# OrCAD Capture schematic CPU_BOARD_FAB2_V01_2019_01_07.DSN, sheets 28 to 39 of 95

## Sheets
28 079 P3V3_STBY: size B
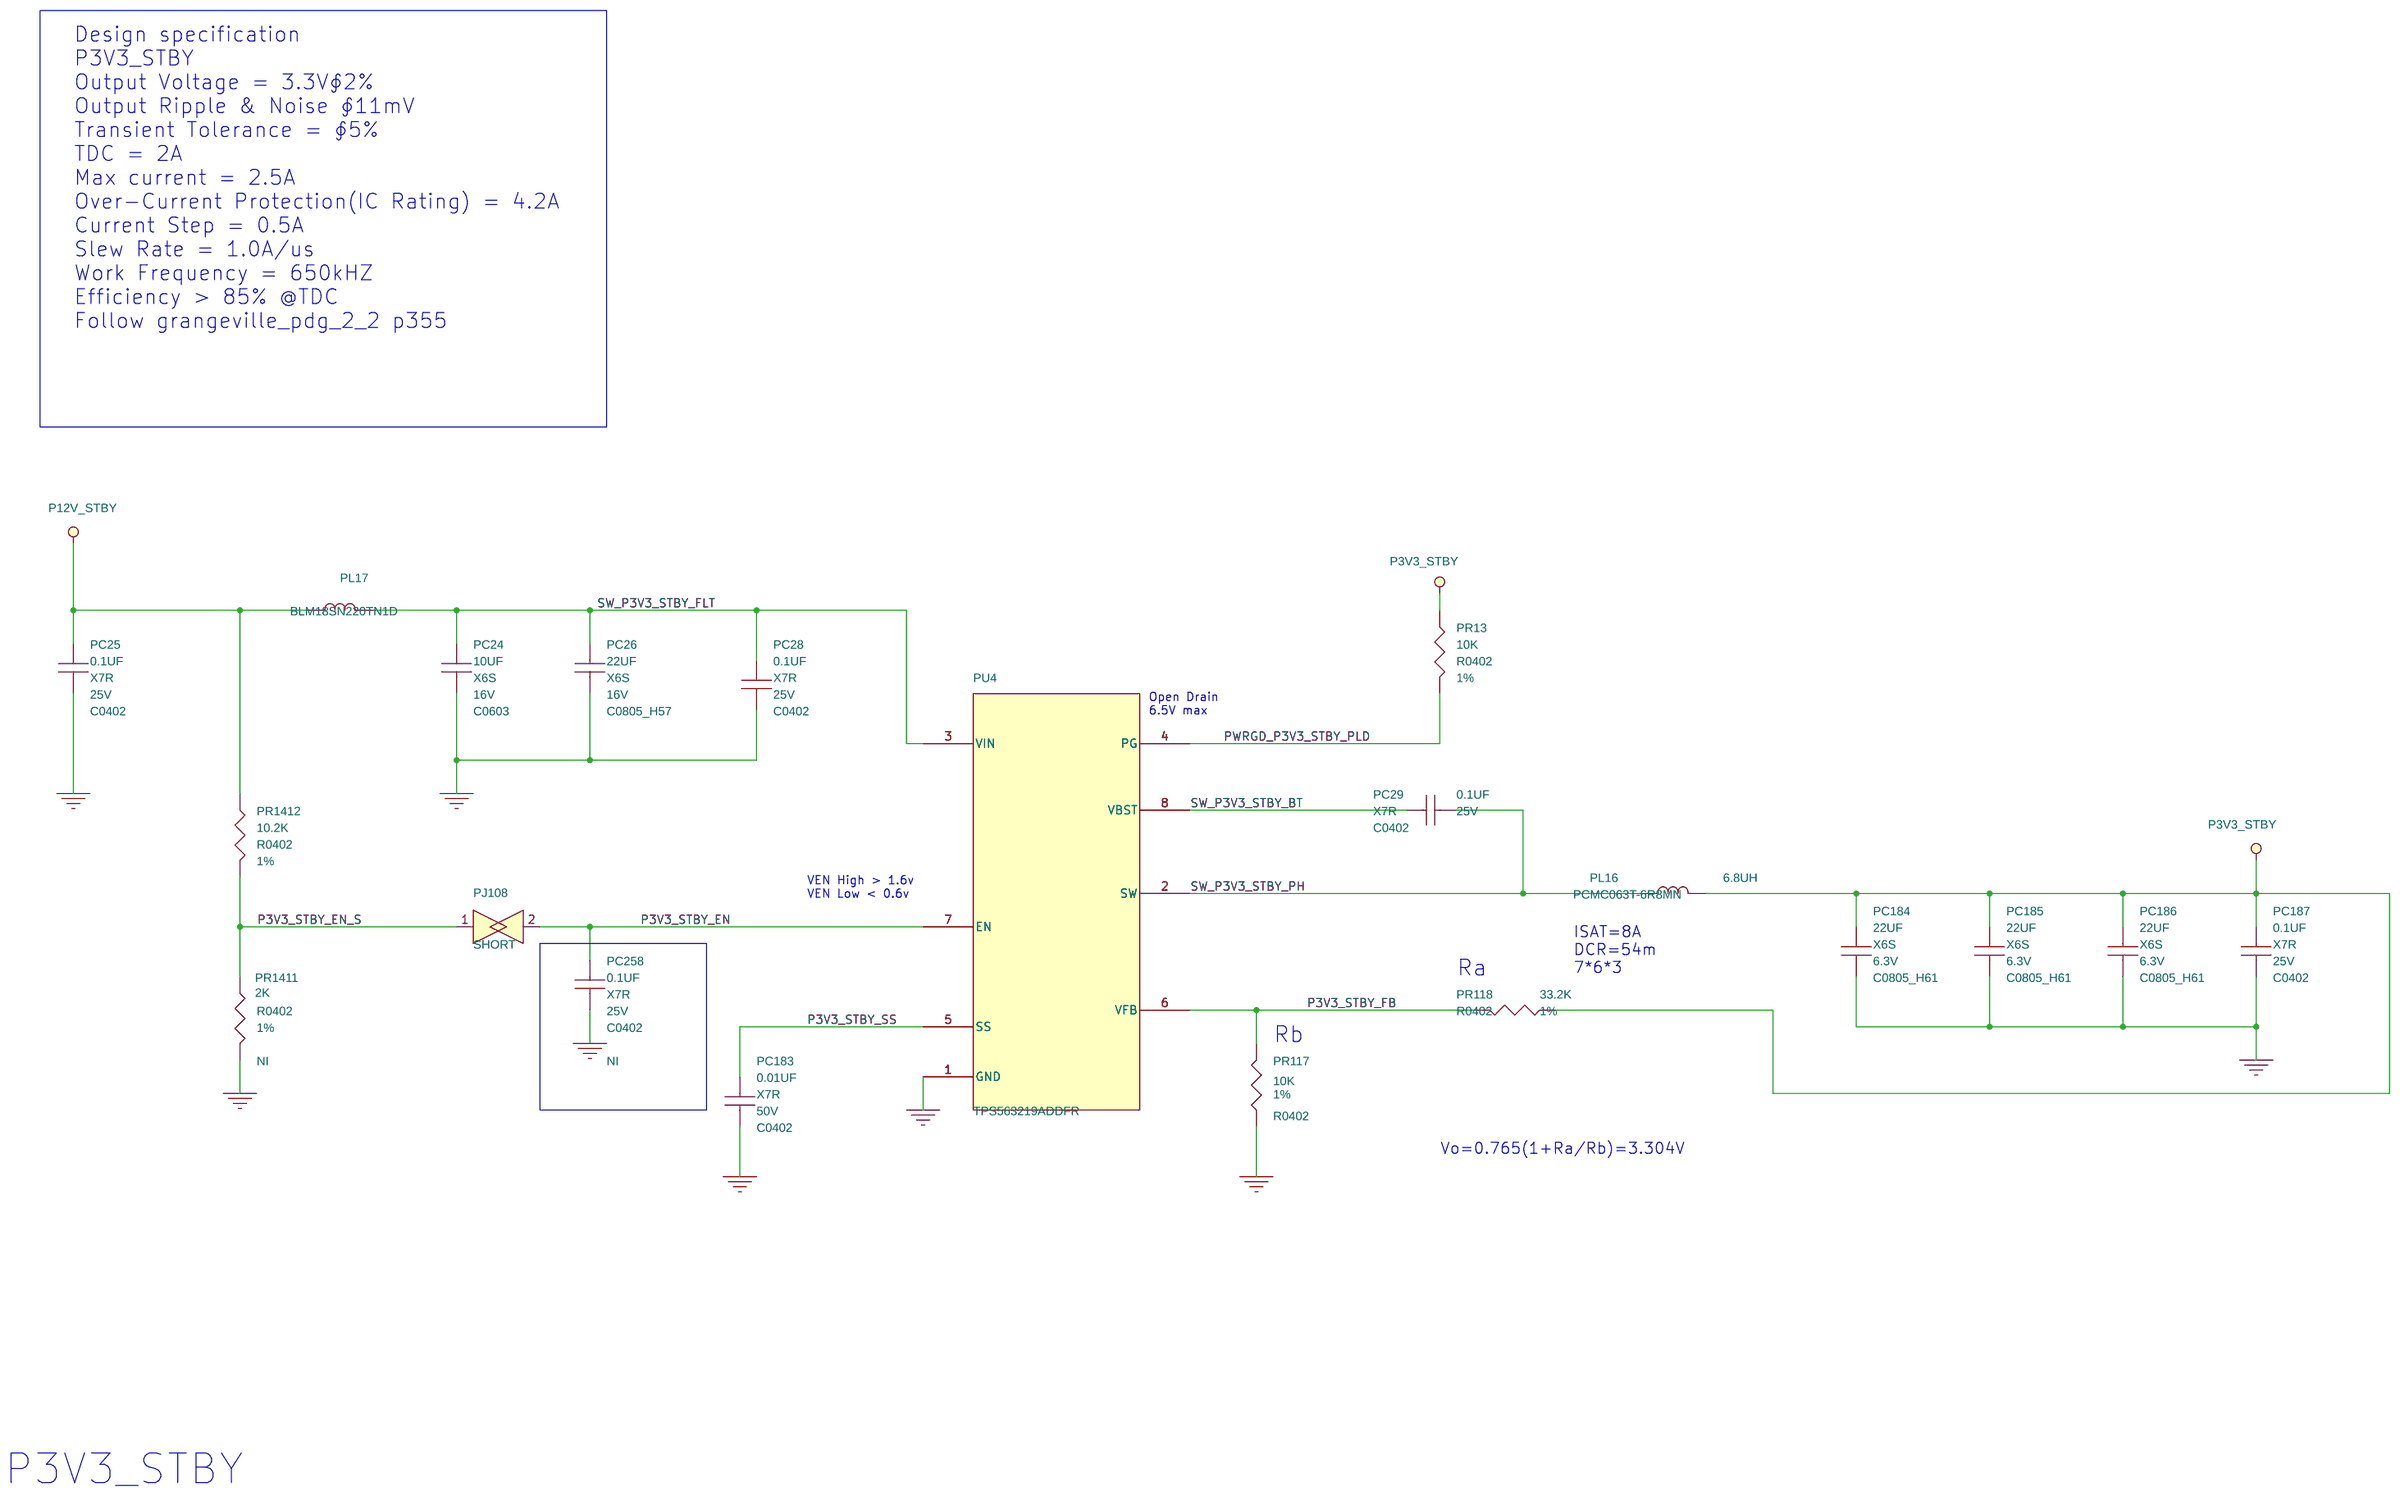
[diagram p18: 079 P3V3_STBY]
29 078 BLANK
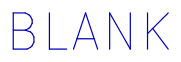
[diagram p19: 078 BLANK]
30 014 SPI_STRUCTURE
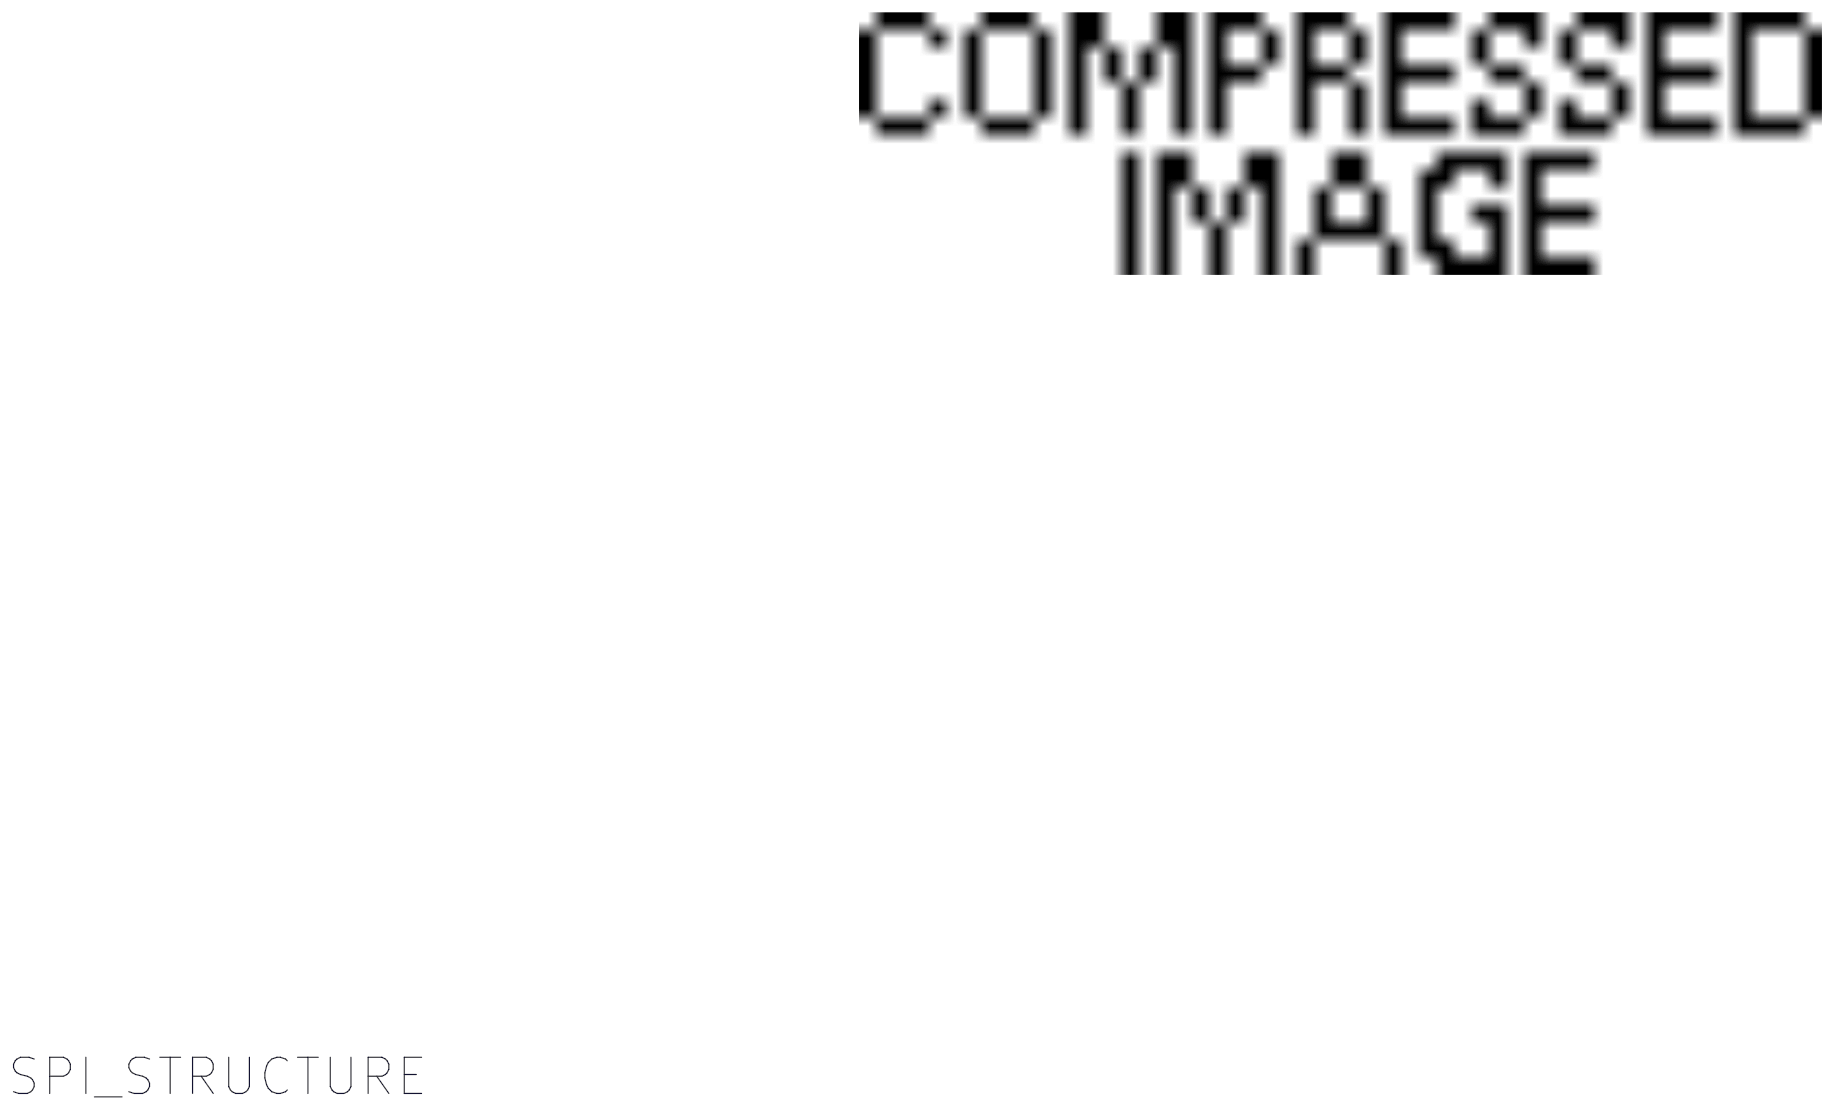
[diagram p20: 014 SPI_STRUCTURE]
31 083 P1V5_PCH: size B
32 090 P3V3 SWITCH: size B
33 001 COVER PAGE
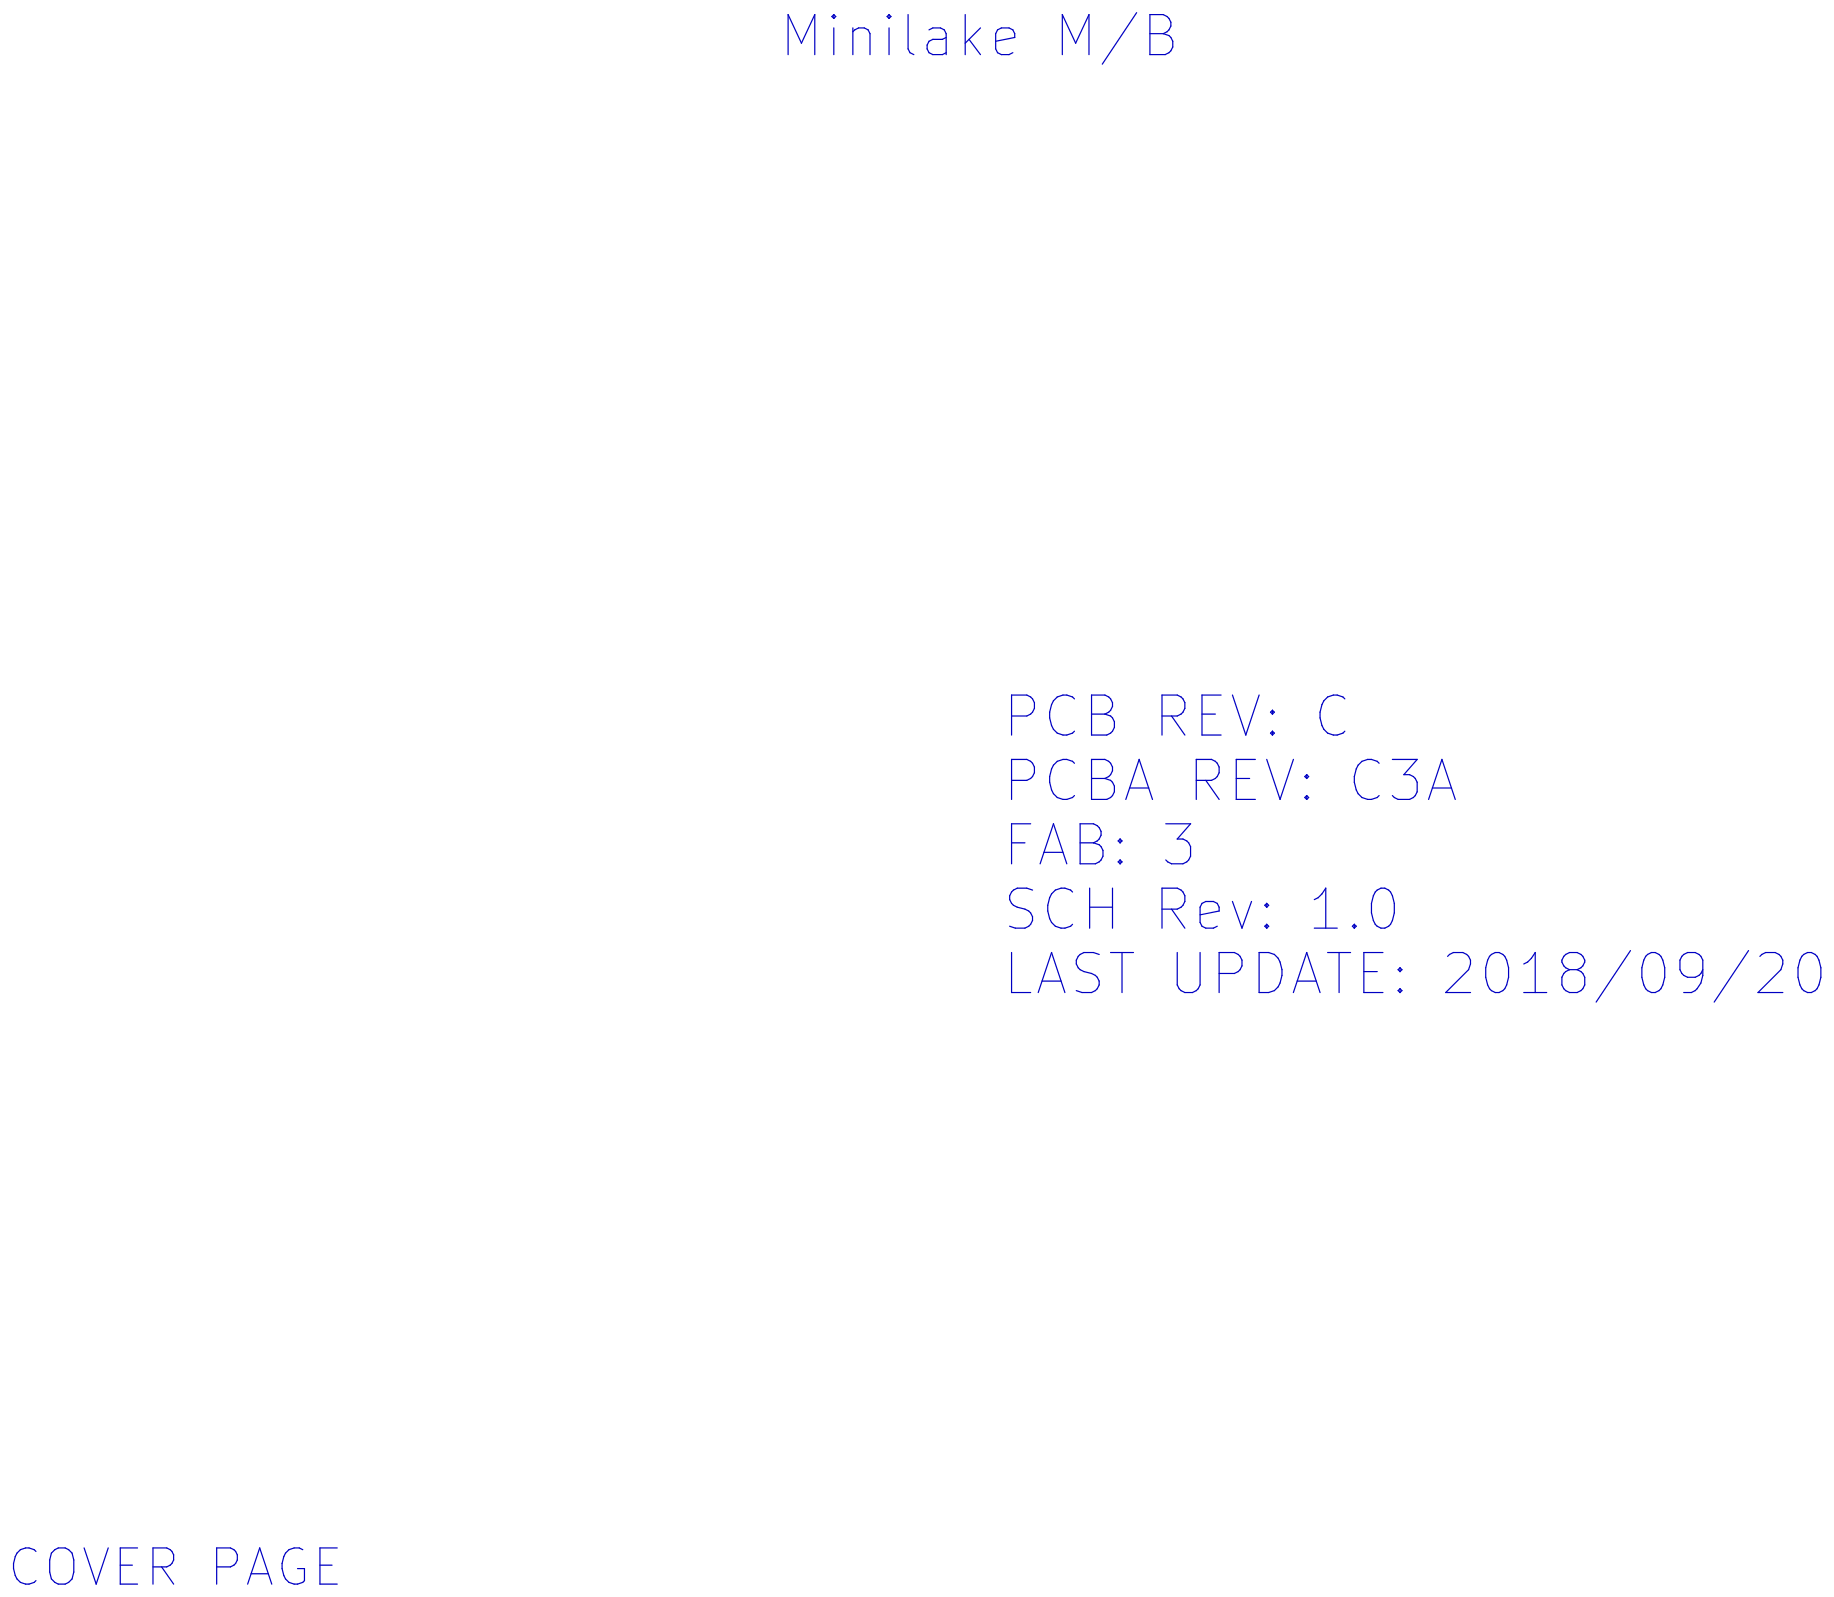
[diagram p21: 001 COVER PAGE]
34 002 PAGE INDEX
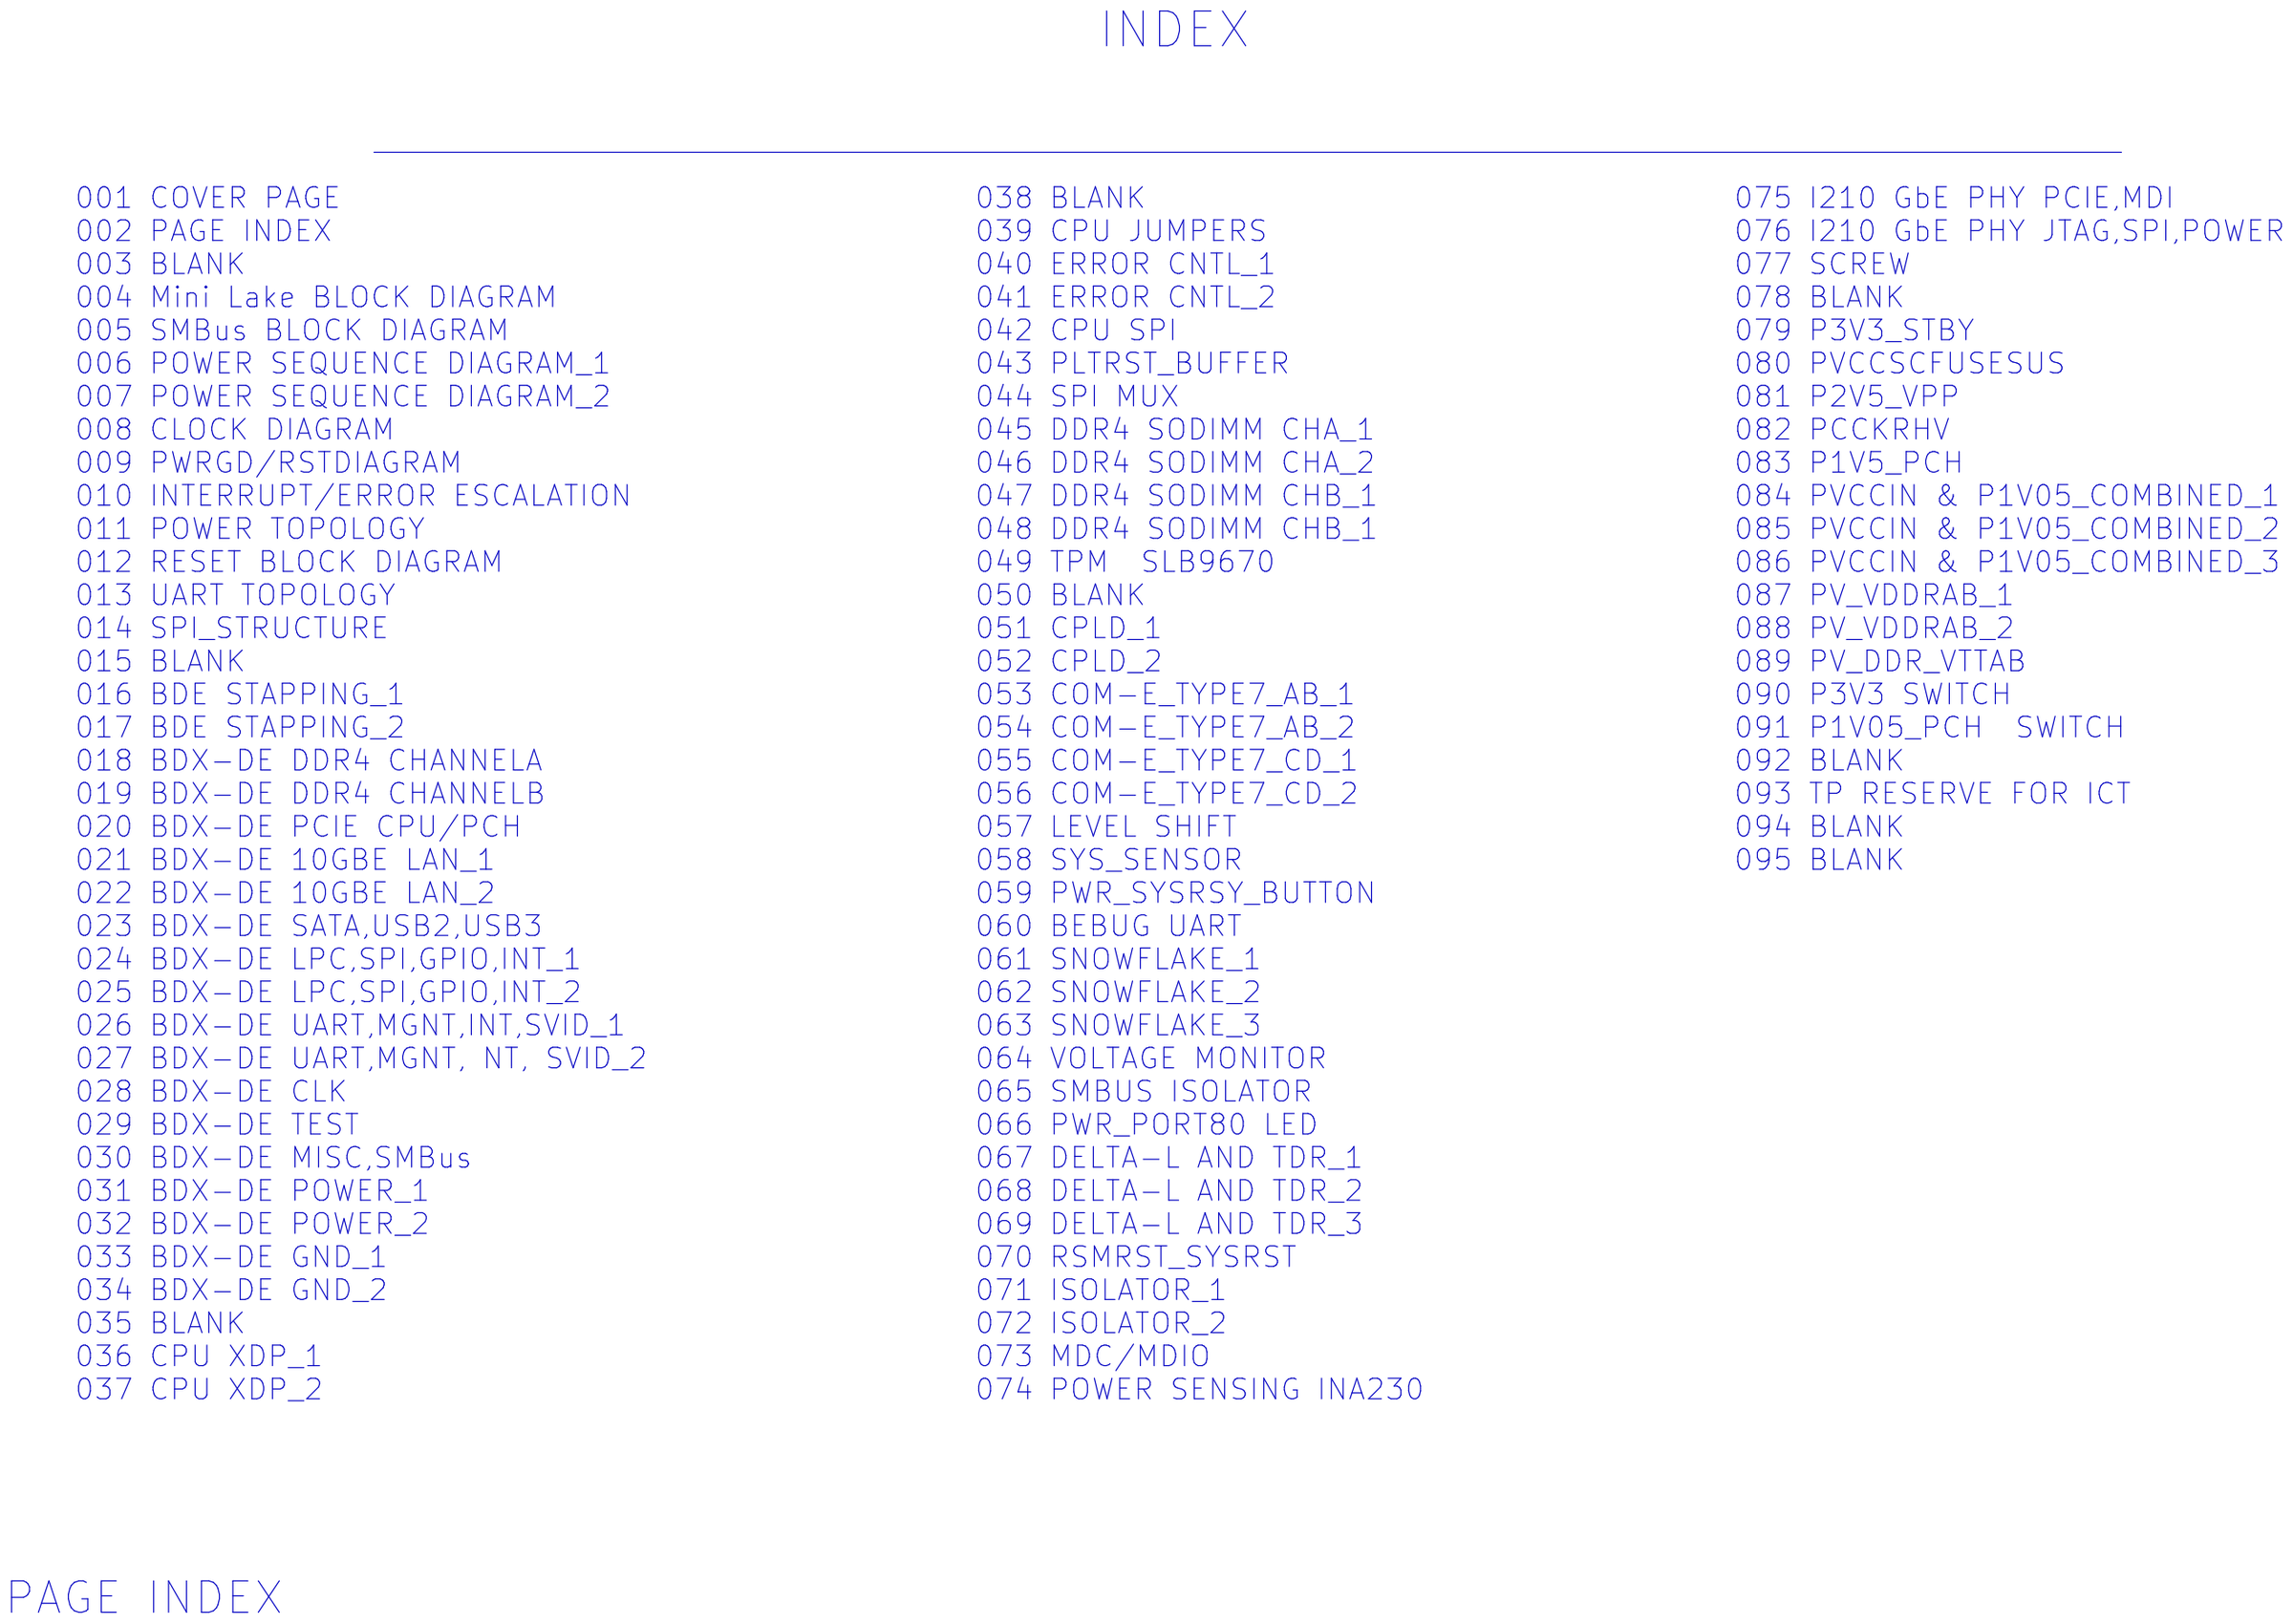
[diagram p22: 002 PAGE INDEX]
35 003 BLANK
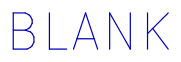
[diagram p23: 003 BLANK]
36 005 SMBus BLOCK DIAGRAM
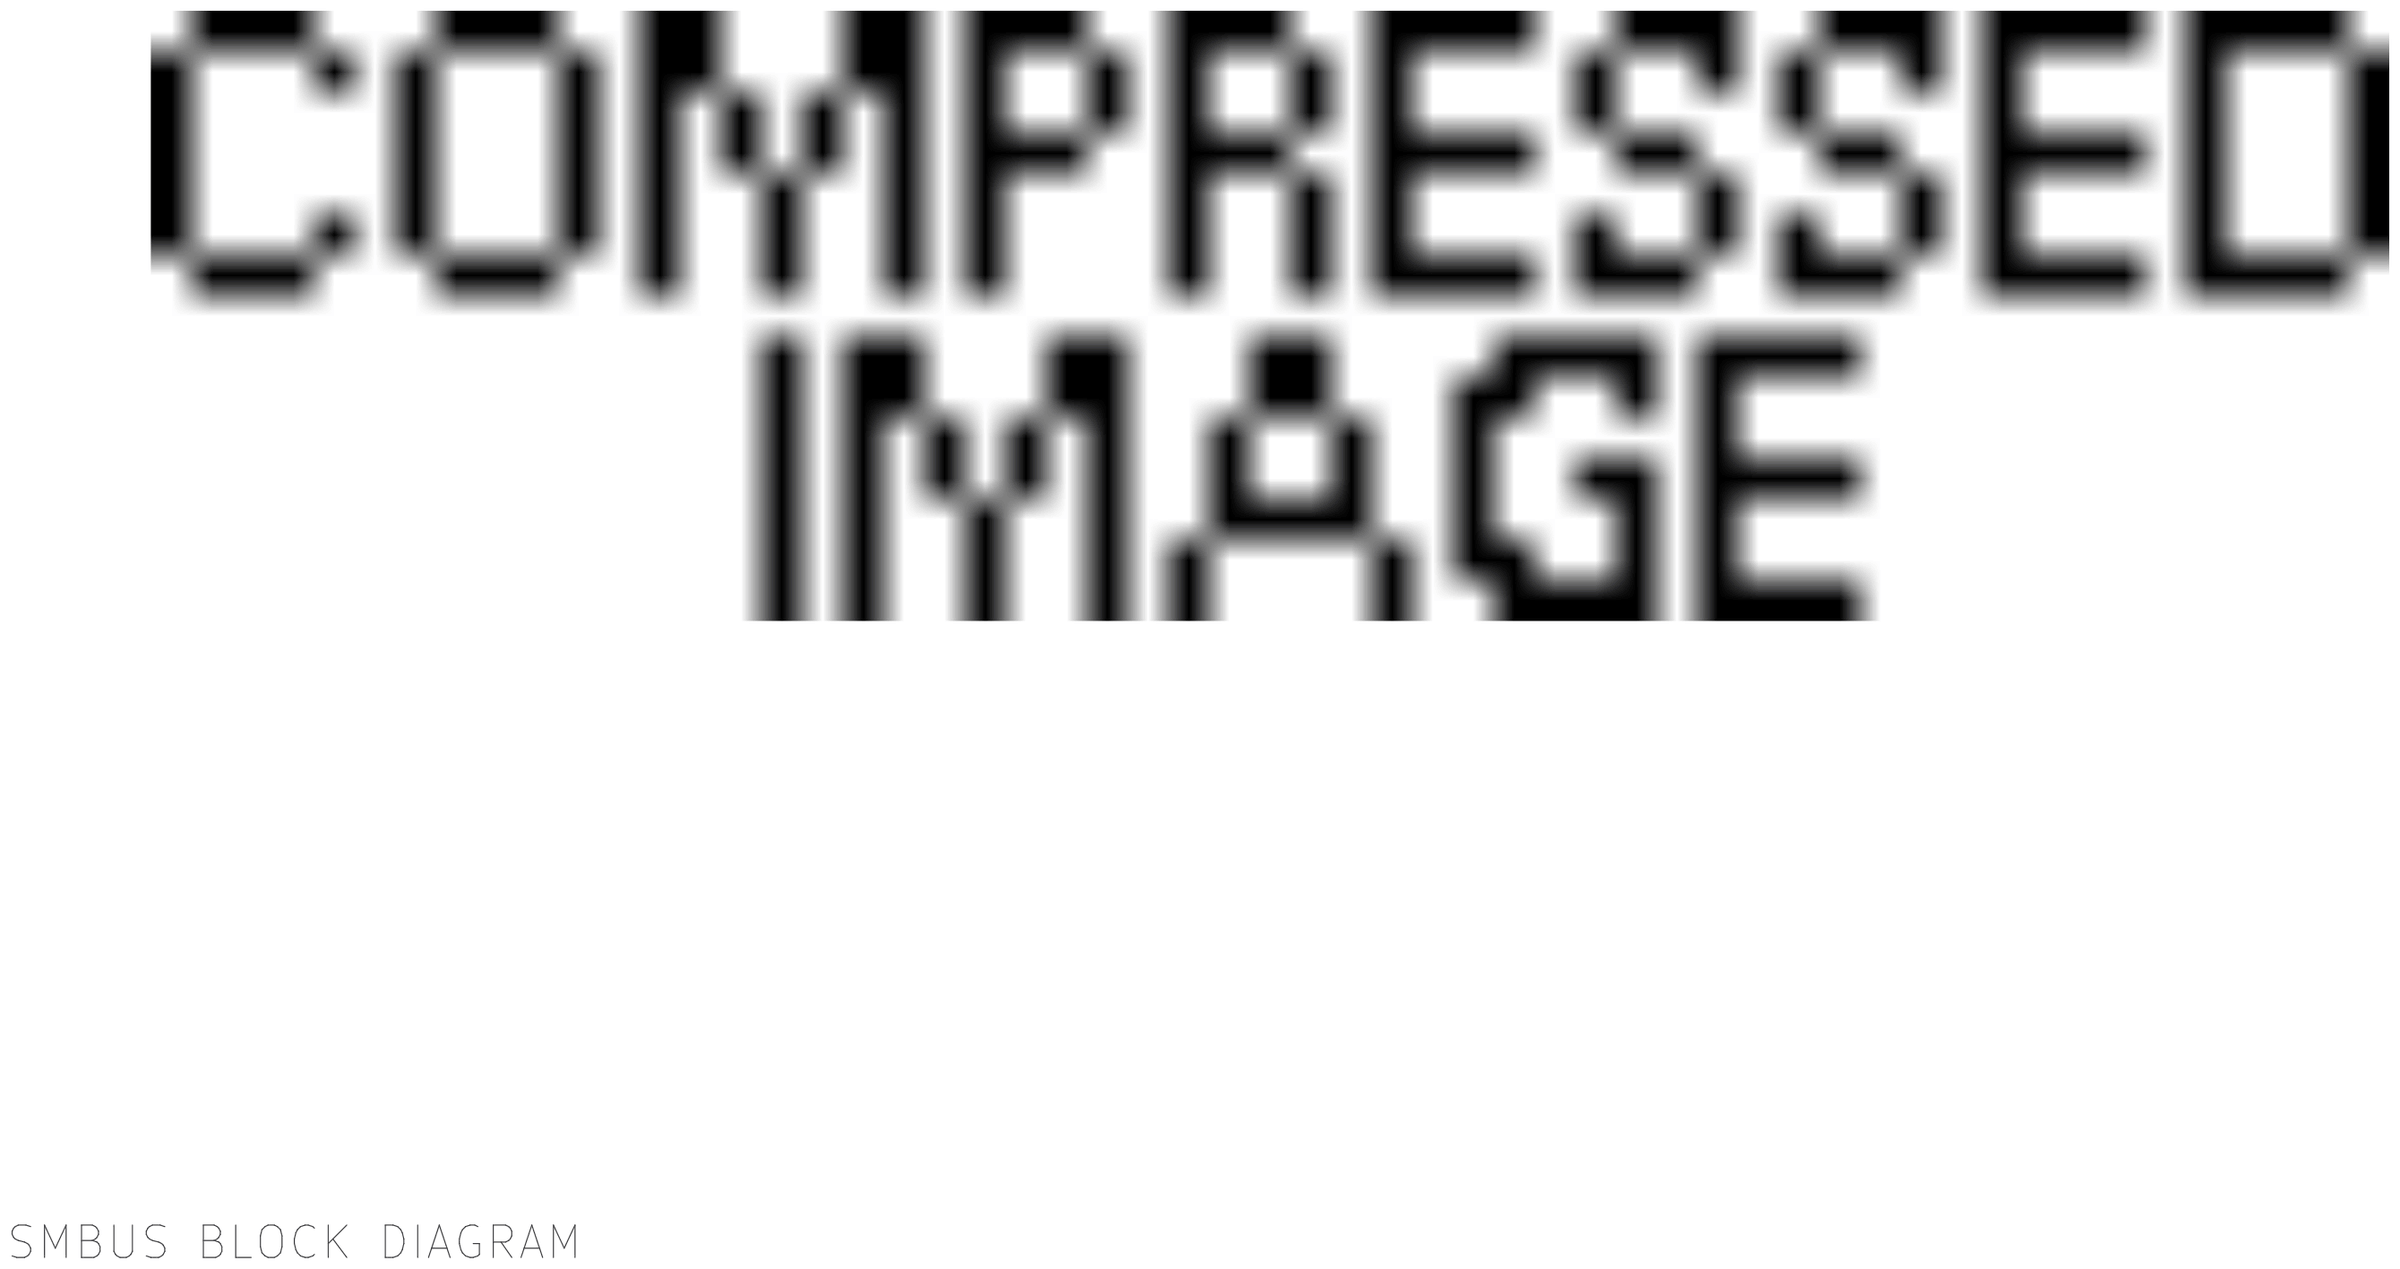
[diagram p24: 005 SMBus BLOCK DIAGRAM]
37 006 POWER SEQUENCE DIAGRAM_1
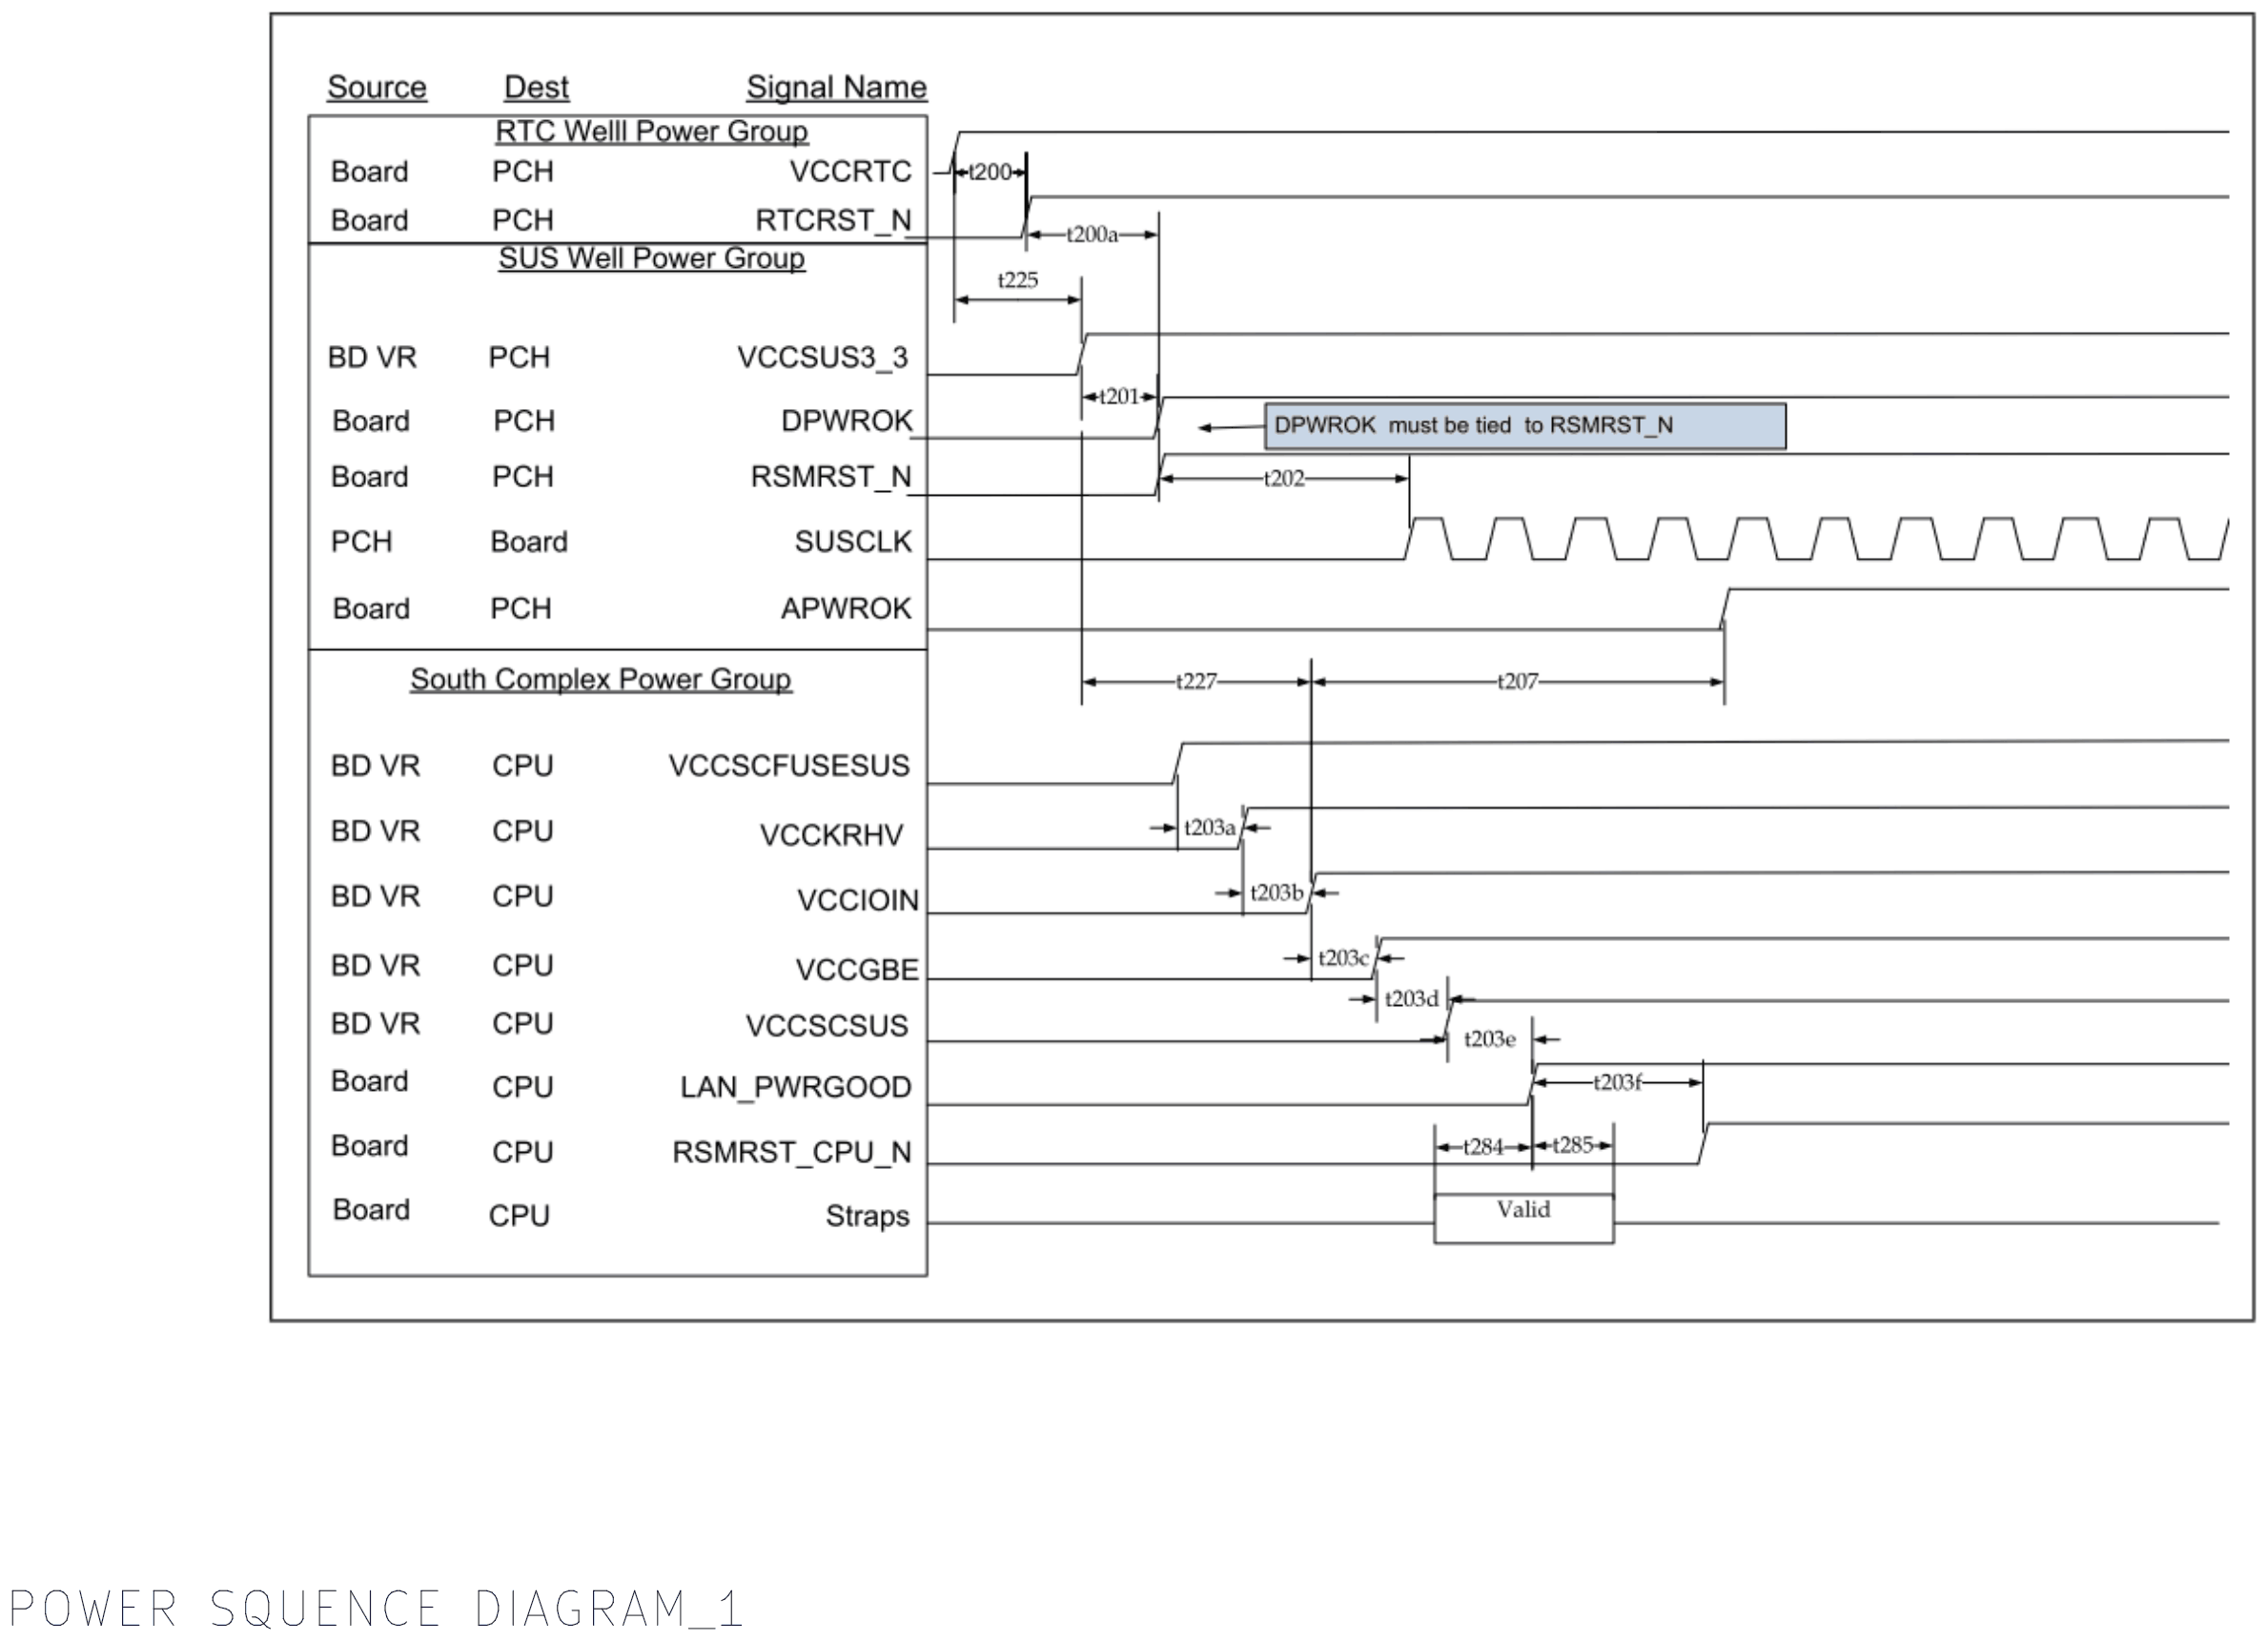
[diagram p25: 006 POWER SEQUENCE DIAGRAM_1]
38 008 CLOCK DIAGRAM
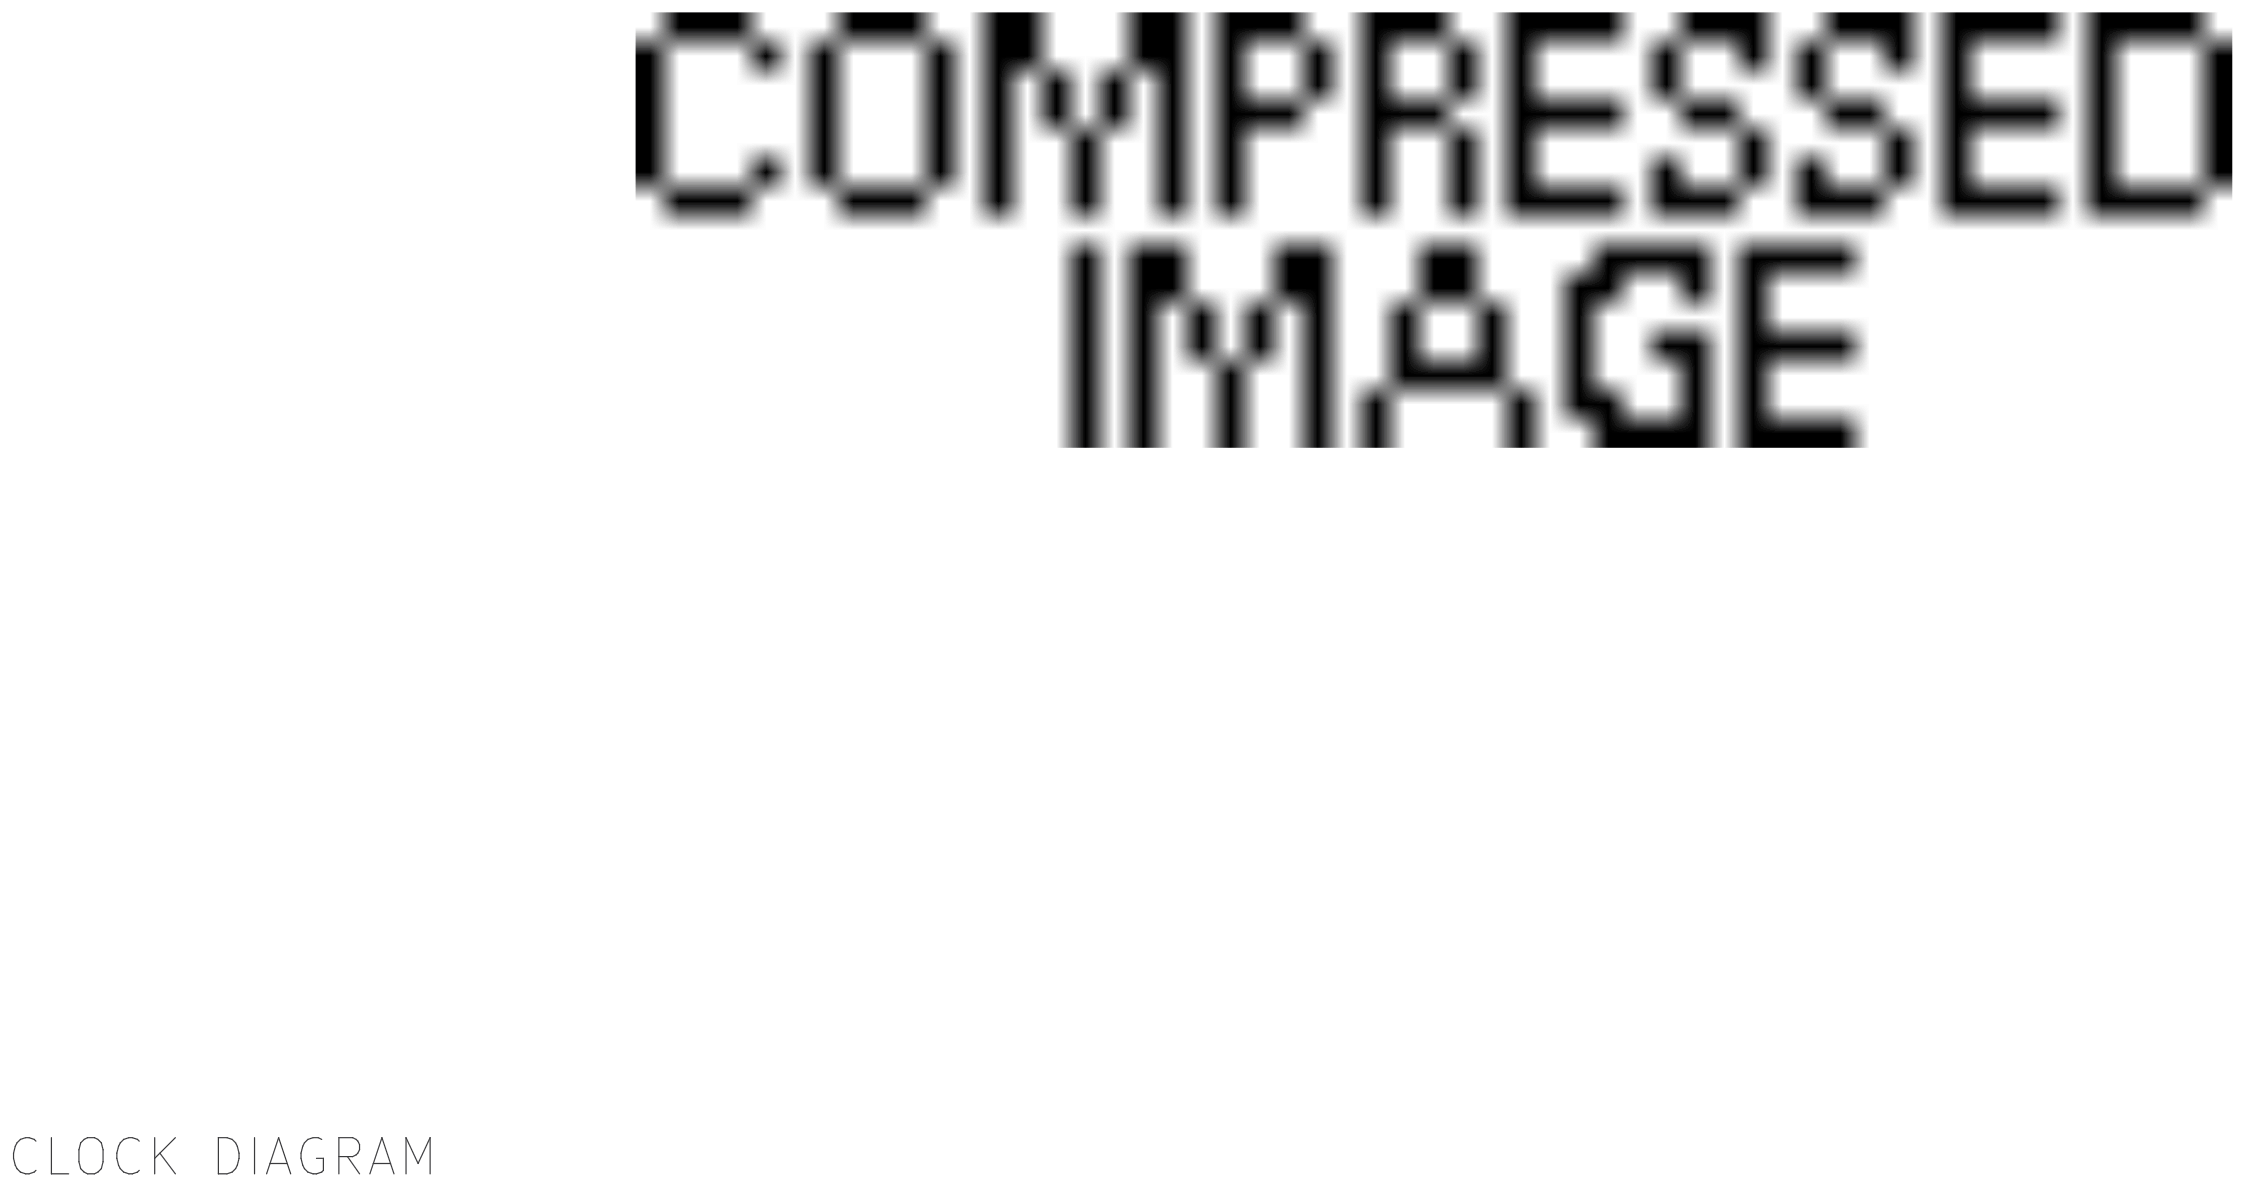
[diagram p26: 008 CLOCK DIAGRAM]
39 013 UART DIAGRAM
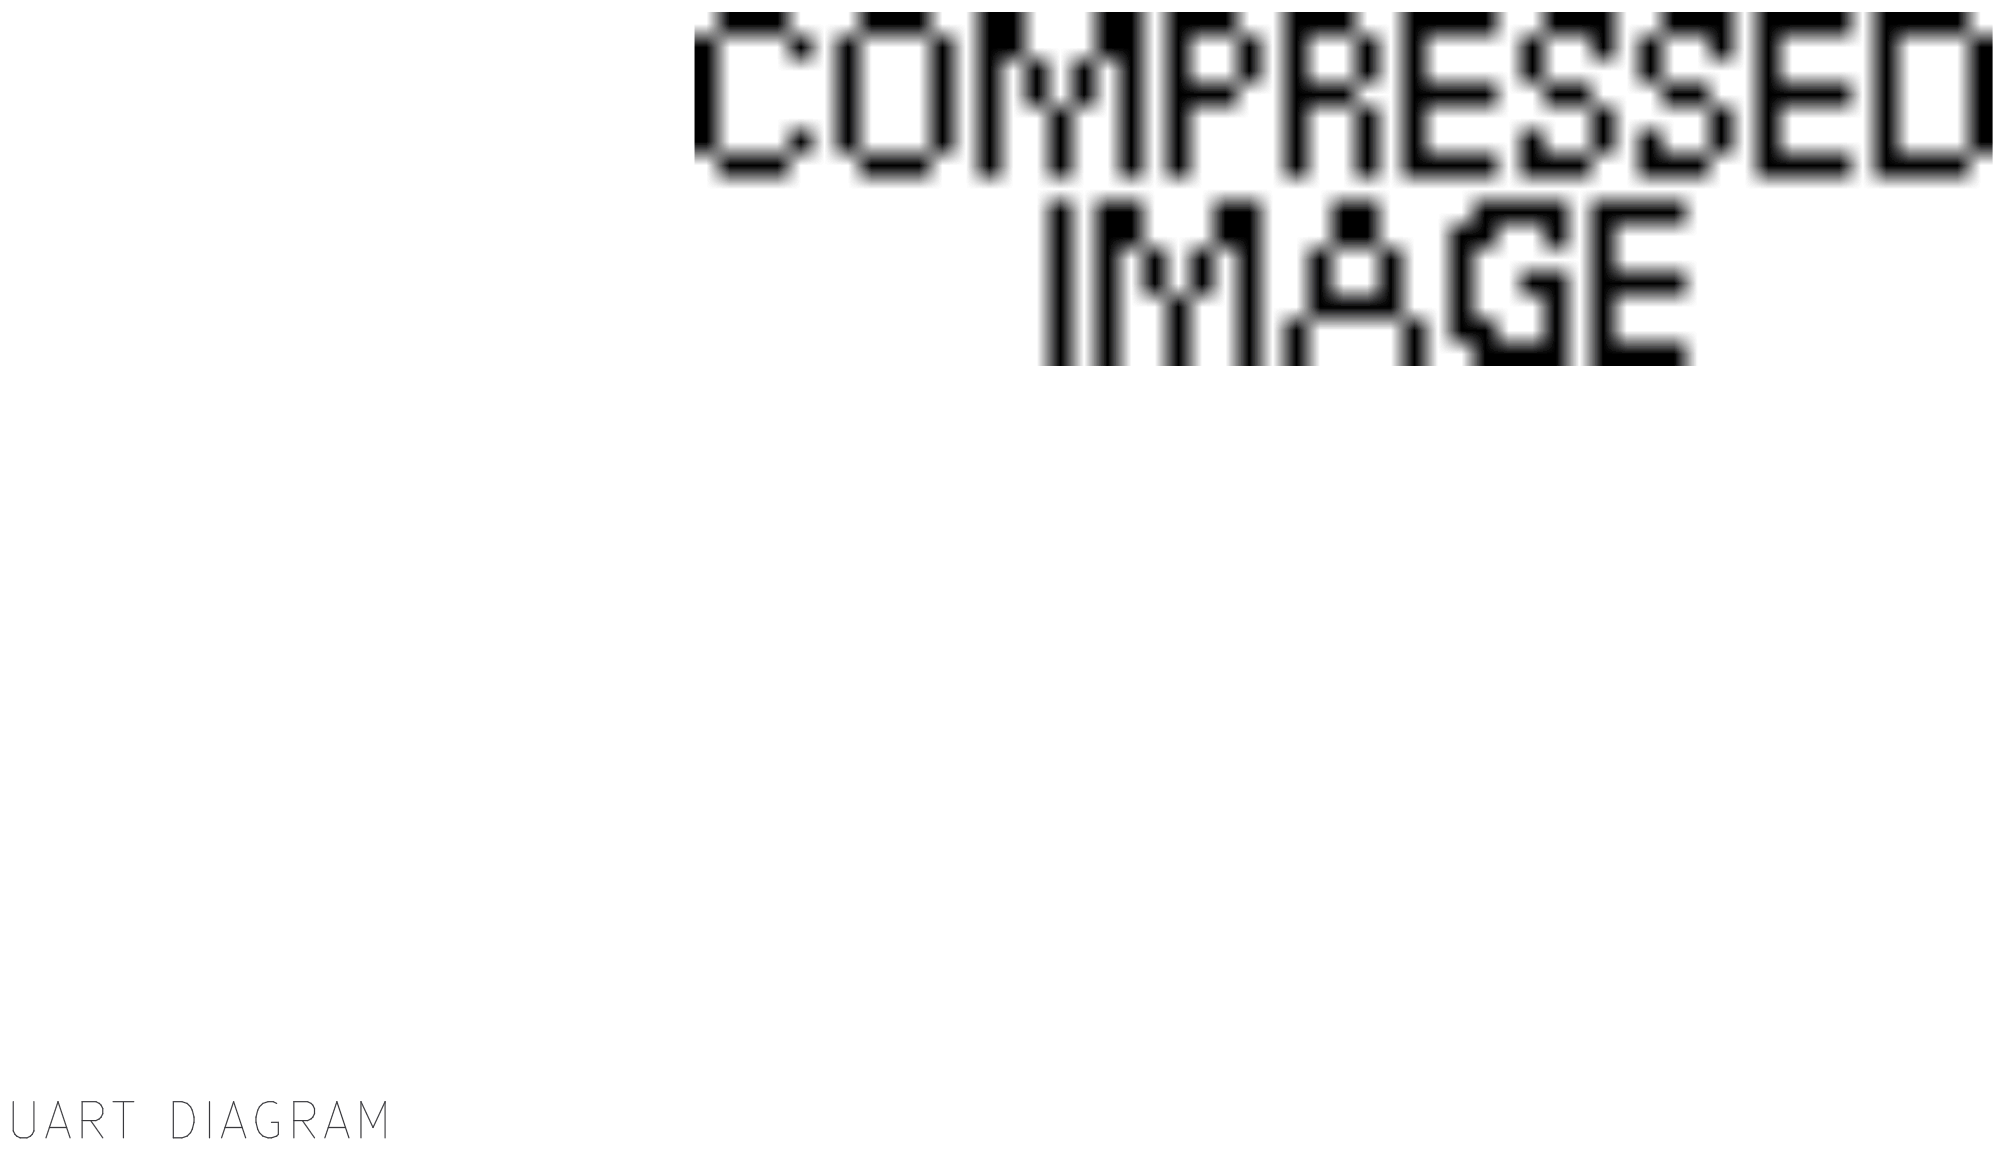
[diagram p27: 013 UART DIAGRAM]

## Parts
sheet 079 P3V3_STBY
PC24  10UF  [C0603]
PC25  0.1UF  [C0402]
PC26  22UF  [C0805_H57]
PC28  0.1UF  [C0402]
PC29  0.1UF  [C0402]
PC183  0.01UF  [C0402]
PC184  22UF  [C0805_H61]
PC185  22UF  [C0805_H61]
PC186  22UF  [C0805_H61]
PC187  0.1UF  [C0402]
PC258  0.1UF  [C0402]
PJ108  SHORT  [SHORT_R0402]
PL16  6.8UH  [L_PCMC063T]
PL17  BLM18SN220TN1D  [L0603]
PR13  10K  [R0402]
PR117  10K  [R0402]
PR118  33.2K  [R0402]
PR1411  2K  [R0402]
PR1412  10.2K  [R0402]
PU4  TPS563219ADDFR  [SOT23-8_0-65_2-9X1-6XA]
sheet 083 P1V5_PCH
PC30  0.1UF  [C0402]
PC33  1UF  [C0402]
PC42  10UF  [C0805_H57]
PC103  10UF  [C0805_H57]
PC261  0.1UF  [C0402]
PR14  10K  [R0402]
PR15  11.3K  [R0402]
PR16  24K  [R0402]
PU7  RT9059-15GQW  [DFN10_THXE]
R1165  33.2  [R0402]
sheet 090 P3V3 SWITCH
C1  0.1UF  [C0402]
PC188  0.1UF  [C0402]
PC189  22UF  [C0805_H61]
PC190  22UF  [C0805_H61]
PC191  0.1UF  [C0402]
PC263  0.1UF  [C0402]
PR119  10K  [R0402]
PU5  NCP45540IMNTWG-H  [DFN12_THXF]
Q9  2N7002KDW  [SOT363XD]
R1169  33.2  [R0402]
R1438  4.7K  [R0402]
R1439  33.2  [R0402]

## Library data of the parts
PC24 = CAP_NP: CAP CHIP 10UF 16V(+-20%,X6S,0603)MUR; CLASS: DISCRETE; CMPLS_LVL: EP(V1); From_pj: JBW-WILLIAM; Lifecycle: Comp-Approve; MATERIAL: X6S; Manuf_PN: GRM188C81C106M; Manuf_name: MURATA ERIE N.A. INC TAIWAN BRANCH Okayama Murata Mfg.Co.,Ltd.Wakura Murata Mfg. Co., Ltd.; Manuftr: MUR; Part_Type: *LF_C0603; RD_CMPLS_LVL: EP(V1); TOLERANCE: 20%; VOLTAGE: 16V
PC25 PC188 PC191 = CAP_NP: CAP CHIP 0.1U 25V(+-10%,X7R,0402); CLASS: DISCRETE; Data: YGO_CA-CC-SC SERIES.pdf; From_pj: F03-KC; Lifecycle: Comp-Approve; MATERIAL: X7R; Manuf_PN: CC0402KRX7R8BB104; Manuf_name: YAGEO CORPORATION; Manufacturer: MAT; Manuftr: YGO; Part_Type: *LF_C0402; RD_CMPLS_LVL: EP(V1); REUSE_ANNOTATE: TRUE; SIDE: TOP; Standard: End of Design; TOLERANCE: 10%; Top_Bot: TOP; VOLTAGE: 25V; fp_ECN: 0402 SERIES_LL34.xls
PC26 = CAP_NP: CAP CHIP 22U 16V(+-20%,X6S,0805); CLASS: DISCRETE; Data: MUR_GRM21BC81C226ME44L.pdf; From_pj: F08-ATLUS; Lifecycle: Comp-Approve; MATERIAL: X6S; Manuf_PN: GRM21BC81C226M; Manuf_name: MURATA ERIE N.A. INC TAIWAN BRANCH Okayama Murata Mfg.Co.,Ltd.Wakura Murata Mfg.; Manufacturer: MAT; Manuftr: MUR; Part_Type: *LF_C0805; RD_CMPLS_LVL: EP(V1); REUSE_ANNOTATE: TRUE; TOLERANCE: 20%; VOLTAGE: 16V
PC28 = CAP_NP: CAP CHIP 0.1U 25V(+-10%,X7R,0402); CLASS: DISCRETE; Data: YGO_CA-CC-SC SERIES.pdf; From_pj: F03-KC; Lifecycle: Comp-Approve; MATERIAL: X7R; Manuf_PN: CC0402KRX7R8BB104; Manuf_name: YAGEO CORPORATION; Manufacturer: MAT; Manuftr: YGO; Part_Type: *LF_C0402; RD_CMPLS_LVL: EP(V1); REUSE_ANNOTATE: TRUE; Standard: End of Design; TOLERANCE: 10%; VOLTAGE: 25V; fp_ECN: 0402 SERIES_LL34.xls
PC29 = CAP_NP: CAP CHIP 0.1U 25V(+-10%,X7R,0402); CLASS: DISCRETE; Data: YGO_CA-CC-SC SERIES.pdf; From_pj: F03-KC; Lifecycle: Comp-Approve; MATERIAL: X7R; Manuf_PN: CC0402KRX7R8BB104; Manuf_name: YAGEO CORPORATION; Manufacturer: RHT; Manuftr: YGO; Part_Type: *LF_C0402; RD_CMPLS_LVL: EP(V1); REUSE_ANNOTATE: TRUE; SIDE: BOT; Standard: End of Design; TOLERANCE: 10%; VOLTAGE: 25V; fp_ECN: 0402 SERIES_LL34.xls
PC183 = CAP_NP: CAP CHIP 0.01U 50V(+-10%,X7R,0402); CLASS: DISCRETE; CMPLS_LVL: EP(V1); Data: MUR_MLCC_20110826.pdf; From_pj: T2B-CHEESE; Lifecycle: Comp-Approve; MATERIAL: X7R; Manuf_PN: WBM155R71H103K; Manuf_name: MURATA ERIE N.A. INC TAIWAN BRANCH Okayama Murata Mfg.Co.,Ltd.; Manufacturer: AVX; Manuftr: MUR; Part_Type: *LF_C0402; RD_CMPLS_LVL: EP(V1); REUSE_ANNOTATE: TRUE; SIDE: TOP; TOLERANCE: 10%; Top_Bot: BOT; VOLTAGE: 50V; fp_ECN: 0402 SERIES_LL34.xls
PC184-PC186 PC189 PC190 = CAP_NP: CAP CHIP 22U 6.3V(+-20%,X6S,0805)MUR; CLASS: DISCRETE; CMPLS_LVL: EP(V1); Data: GRM21BC80J226M.pdf; From_pj: T2H-CF; Lifecycle: Comp-Approve; MATERIAL: X6S; Manuf_PN: GRM21BC80J226M; Manuf_name: MURATA ERIE N.A. INC TAIWAN BRANCH Okayama Murata Mfg.Co.,Ltd.Wakura Murata Mfg.; Manufacturer: AVX; Manuftr: MUR; Part_Type: *LF_C0805; RD_CMPLS_LVL: EP(V1); REUSE_ANNOTATE: TRUE; SIDE: TOP; Standard: End of Design; TOLERANCE: 20%; Top_Bot: BOT; VOLTAGE: 6.3V
PC187 = CAP_NP: CAP CHIP 0.1U 25V(+-10%,X7R,0402); CLASS: DISCRETE; Data: YGO_CA-CC-SC SERIES.pdf; From_pj: F03-KC; Lifecycle: Comp-Approve; MATERIAL: X7R; Manuf_PN: CC0402KRX7R8BB104; Manuf_name: YAGEO CORPORATION; Manufacturer: AVX; Manuftr: YGO; Part_Type: *LF_C0402; RD_CMPLS_LVL: EP(V1); REUSE_ANNOTATE: TRUE; SIDE: TOP; Standard: End of Design; TOLERANCE: 10%; Top_Bot: BOT; VOLTAGE: 25V; fp_ECN: 0402 SERIES_LL34.xls
PC258 PC261 PC263 = CAP_NP: CAP CHIP 0.1U 25V(+-10%,X7R,0402); CLASS: DISCRETE; Data: YGO_CA-CC-SC SERIES.pdf; From_pj: F03-KC; Lifecycle: Comp-Approve; MATERIAL: X7R; Manuf_PN: CC0402KRX7R8BB104; Manuf_name: YAGEO CORPORATION; Manufacturer: MAT; Manuftr: YGO; Not_insert: NI; Part_Type: *LF_C0402; RD_CMPLS_LVL: EP(V1); REUSE_ANNOTATE: TRUE; SIDE: TOP; Standard: End of Design; TOLERANCE: 10%; Top_Bot: TOP; VOLTAGE: 25V; fp_ECN: 0402 SERIES_LL34.xls
PJ108 = JUMPER-2_1: JUMP.SHORT_R0402; CLASS: IO; From_pj: A06-JACK; MATERIAL: MECH; Part_Type: Mech
PL16 = L: IND SMD 6.8UH +-20%,4.5A(PCMC063T-6R8MN); CLASS: DISCRETE; Current_Amp: 4.5A; Data: CYN_PCMC063T-000_A4.pdf; From_pj: XG6-KC; Lifecycle: Comp-Approve; MATERIAL: IND; Manuf_PN: PCMC063T-6R8MN; Manuf_name: CYNTEC CO., LTD.; Manuftr: CYN; Part_Type: *LF_Inductor; RD_CMPLS_LVL: EP(V1); Standard: ##; fp_ECN: L_PCMC063T.doc
PL17 = L: EMI FILTER BLM18SN220TN1D(22,8000MA); CLASS: DISCRETE; Current_Amp: 8000MA; Data: MUR_BLM18SN220TN1D.pdf; From_pj: F08-ATLUS; Lifecycle: Comp-Approve; MATERIAL: IND; Manuf_name: MURATA ERIE N.A. INC TAIWAN BRANCH Okayama Murata Mfg.Co.,; Manuftr: MUR; Part_Type: *LF_Inductor; RD_CMPLS_LVL: EP(V1); SIDE: TOP
PR13 = R: RES CHIP 10K 1/16W +-1% (0402); CLASS: DISCRETE; CMPLS_LVL: EP; Data: WTC_LF_WR SERIES.pdf; From_pj: S82; Lifecycle: Comp-Approve; MATERIAL: CHIP; Manuf_PN: RR0510S-103-FN; Manuf_name: CYNTEC CO.. LTD.; Manufacturer: CYN; Manuftr: CYN; Part_Type: *LF_Resistor; SIDE: BOT; Status: Preferred; TOLERANCE: 1%; WATTAGE: 1/16W; fp_ECN: 0402 SERIES_LL34.xls
PR117 = R: RES CHIP 10K 1/16W +-1% (0402); CLASS: DISCRETE; CMPLS_LVL: EP; Data: WTC_LF_WR SERIES.pdf; From_pj: S82; Lifecycle: Comp-Approve; MATERIAL: CHIP; Manuf_PN: RR0510S-103-FN; Manuf_name: CYNTEC CO.. LTD.; Manuftr: CYN; Part_Type: *LF_Resistor; SIDE: TOP; Status: Preferred; TOLERANCE: 1%; WATTAGE: 1/16W; fp_ECN: 0402 SERIES_LL34.xls
PR118 = R: RES CHIP 33.2K 1/16W +-1% (0402); CLASS: DISCRETE; CMPLS_LVL: EP; Data: WTC_LF_WR SERIES-4.pdf; From_pj: T96-KC; Lifecycle: Comp-Approve; MATERIAL: CHIP; Manuf_PN: WR04X3322FTL; Manuf_name: WALSIN TECHNOLOGY CORPORATION; Manuftr: WTC; Part_Type: *LF_Resistor; SIDE: TOP; Standard: ##; TOLERANCE: 1%; WATTAGE: 1/16W; fp_ECN: 0402 SERIES_LL34.xls
PR1411 = R: RES CHIP 2K 1/16W +-1%(0402)AEC; CLASS: DISCRETE; From_pj: T2HV-RONNY; Lifecycle: Comp-Release Qty; MATERIAL: CHIP; Manuf_PN: AC0402FR-072KL; Manuf_name: YAGEO CORPORATION; Manuftr: YGO; Not_insert: NI; Part_Type: *LF_Resistor; RD_CMPLS_LVL: EP(V1); TOLERANCE: 1%; WATTAGE: 1/16W; fp_ECN: 0402 SERIES_LL34.xls
PR1412 = R: RES CHIP 10.2K 1/16W +-1%(0402); CLASS: DISCRETE; CMPLS_LVL: EP; Data: YGO_RC SERIES_1.pdf; From_pj: S75T-TERRY; Lifecycle: Comp-Approve; MATERIAL: CHIP; Manuf_PN: RC0402FR-0710K2L; Manuf_name: YAGEO CORPORATION; Manuftr: YGO; Part_Type: *LF_Resistor; TOLERANCE: 1%; WATTAGE: 1/16W; fp_ECN: 0402 SERIES_LL34.xls
PU4 = TPS563219DDFR: IC OTHER(8P)TPS563219ADDFR(SOT-23-THIN); CLASS: IC; Data: TIC_TPS563219ADDFR.pdf; From_pj: S5G-KENNETH; Lifecycle: Comp-Release Qty; MATERIAL: IC; Manuf_name: TEXAS INSTRUMENTS SUPPLY CO.,; Manuftr: TIC; Part_Type: *LF_Chipset; RD_CMPLS_LVL: EP(V1); Standard: Potential
PC30 = CAP_NP: CAP CHIP 0.1U 16V(10%.X7R.0402); CLASS: DISCRETE; CMPLS_LVL: EP(V1); Data: MUR_LF_CAP SERIES_1.pdf; From_pj: S5A-TRAVIS; Lifecycle: Comp-Approve; MATERIAL: X7R; Manuf_PN: WBM155R71C104K; Manuf_name: MURATA ERIE N.A. INC TAIWAN BRANCH Okayama Murata Mfg.Co..Ltd. Wakura Murata Mfg; Manufacturer: AVX; Manuftr: MUR; Part_Type: *LF_C0402; RD_CMPLS_LVL: EP(V1); TOLERANCE: 10%; Top_Bot: BOT; VOLTAGE: 16V; fp_ECN: 0402 SERIES_LL34.xls
PC33 = CAP_NP: CAP CHIP 1UF 10V(+-10%,X6S,0402); CLASS: DISCRETE; CMPLS_LVL: EP(V1); Data: MUR_LF_CAPSERIES_19JUN2012.pdf; From_pj: T6M-MARKCHEN; Lifecycle: Comp-Approve; MATERIAL: X6S; Manuf_PN: GRM155C81A105K; Manuf_name: MURATA ERIE N.A. INC TAIWAN BRANCH Okayama Murata Mfg.Co.,; Manufacturer: AVX; Manuftr: MUR; Part_Type: *LF_C0402; RD_CMPLS_LVL: EP(V1); REUSE_ANNOTATE: TRUE; Standard: End of Design; TOLERANCE: 10%; Top_Bot: BOT; VOLTAGE: 10V; fp_ECN: 0402 SERIES_LL34.xls
PC42 PC103 = CAP_NP: CAP CHIP 10U,4V(+-20%,X6S,0805)MUR; CLASS: DISCRETE; CMPLS_LVL: EP(V1); Data: MUR_GRM21BC80G106M.pdf; From_pj: T2H-DUNCAN; Lifecycle: Comp-Approve; MATERIAL: X6S; Manuf_PN: GRM21BC80G106M; Manuf_name: MURATA ERIE N.A. INC TAIWAN BRANCH Okayama Murata Mfg.Co..Ltd.Wakura Murata Mfg.; Manuftr: MUR; Part_Type: *LF_C0805; RD_CMPLS_LVL: EP(V1); TOLERANCE: 20%; VOLTAGE: 4V
PR14 = R: RES CHIP 10K 1/16W +-1% (0402); CLASS: DISCRETE; CMPLS_LVL: EP; Data: WTC_LF_WR SERIES.pdf; From_pj: S82; Lifecycle: Comp-Approve; MATERIAL: CHIP; Manuf_PN: RR0510S-103-FN; Manuf_name: CYNTEC CO.. LTD.; Manufacturer: CYN; Manuftr: CYN; Part_Type: *LF_Resistor; Status: Preferred; TOLERANCE: 1%; WATTAGE: 1/16W; fp_ECN: 0402 SERIES_LL34.xls
PR15 = R: RES CHIP 11.3K 1/16W +-1%(0402); CLASS: DISCRETE; CMPLS_LVL: EP; Data: RHT_LF_RES SERIES-2.pdf; From_pj: S2F-WENLUNG; MATERIAL: CHIP; Manuf_PN: CR0211K3F002S; Manuf_name: RTECH TECHNOLOGY CO..LTD.(Compostar); Manufacturer: RLC; Manuftr: RHT; Not_insert: NI; Part_Type: *LF_Resistor; TOLERANCE: 1%; TOP_BOT: TOP; WATTAGE: 1/16W; fp_ECN: 0402 SERIES_LL34.xls
PR16 = R: RES CHIP 24K 1/16W +-1%(0402); CLASS: DISCRETE; CMPLS_LVL: EP(V1); Data: TAI_LF_RM SERIES-2.pdf; From_pj: BX8-DANNY; Lifecycle: Comp-Approve; MATERIAL: CHIP; Manuf_PN: RM04FTN2402; Manuf_name: TA-I TECHNOLOGY CO..LTD.; Manufacturer: RLC; Manuftr: TAI; Not_insert: NI; Part_Type: *LF_Resistor; RD_CMPLS_LVL: EP(V1); TOLERANCE: 1%; TOP_BOT: TOP; WATTAGE: 1/16W; fp_ECN: 0402 SERIES_LL34.xls
PU7 = RT9059GQW: IC OTHER(10P) RT9059-15GQW(WDFN); CLASS: IC; Data: RTK_RT9059_REV201207.pdf; From_pj: S2B-ALAN; Lifecycle: Comp-Approve; MATERIAL: IC; Manuf_name: RICHTEK TECHNOLOGY CORPORATION; Manuftr: RTK; Part_Type: *LF_Chipset; RD_CMPLS_LVL: EP(V1)
R1165 R1169 R1439 = R: RES CHIP 33.2 1/16W +-1%(0402); CLASS: DISCRETE; CMPLS_LVL: EP; Data: CYN_LF_RL SERIES.pdf; From_pj: A06-EDISON; Lifecycle: Comp-Approve; MATERIAL: CHIP; Manuf_PN: RR0510S-33R2-FN; Manuf_name: CYNTEC CO.. LTD.; Manuftr: CYN; Part_Type: *LF_Resistor; TOLERANCE: 1%; WATTAGE: 1/16W; fp_ECN: 0402 SERIES_LL34.xls
C1 = CAP_NP: CAP CHIP 0.1U 16V(10%.X7R.0402); CLASS: DISCRETE; CMPLS_LVL: EP(V1); Data: MUR_LF_CAP SERIES_1.pdf; From_pj: S5A-TRAVIS; Lifecycle: Comp-Approve; MATERIAL: X7R; Manuf_PN: WBM155R71C104K; Manuf_name: MURATA ERIE N.A. INC TAIWAN BRANCH Okayama Murata Mfg.Co..Ltd. Wakura Murata Mfg; Manufacturer: AVX; Manuftr: MUR; Not_insert: NI; Part_Type: *LF_C0402; RD_CMPLS_LVL: EP(V1); TOLERANCE: 10%; Top_Bot: BOT; VOLTAGE: 16V; fp_ECN: 0402 SERIES_LL34.xls
PR119 = R: RES CHIP 10K 1/16W +-1% (0402); CLASS: DISCRETE; CMPLS_LVL: EP; Data: WTC_LF_WR SERIES.pdf; From_pj: S82; Lifecycle: Comp-Approve; MATERIAL: CHIP; Manuf_PN: RR0510S-103-FN; Manuf_name: CYNTEC CO.. LTD.; Manufacturer: CYN; Manuftr: CYN; Part_Type: *LF_Resistor; Status: Preferred; TOLERANCE: 1%; TOP_BOT: BOT; WATTAGE: 1/16W; fp_ECN: 0402 SERIES_LL34.xls
PU5 = NCP45540IMNTWGH: IC OTHER(12P)NCP45540IMNTWG-H(DFN); CLASS: IC; CMPLS_LVL: EP(V1); Data: ONS_NCP45540IMNTWG-H_AL045540001.pdf; From_pj: F09-MARK; Lifecycle: Comp-Approve; MATERIAL: IC; Manuf_name: ON SEMICONDUCTOR; Manuftr: ONS; Part_Type: *LF_Chipset; RD_CMPLS_LVL: EP(V1)
Q9 = MOSFET_DUAL_6P: TRANS MOS 2N7002KDW(60V115MA,0.2W)SOT363; CLASS: IC; CMPLS_LVL: EP(V1); Data: PJT_2N7002KDW.pdf; From_pj: F06S-KENG-YU; Lifecycle: Comp-Approve; MATERIAL: IC; Manuf_name: PAN JIT INTERNATIONAL INC.; Manuftr: PJT; Part_Type: *LF_Semiconductor; RD_CMPLS_LVL: EP(V1)
R1438 = R: RES CHIP 4.7K 1/16W +-5% (0402); BOM: TI; CLASS: DISCRETE; CMPLS_LVL: EP; Data: WTC_LF_WR SERIES.pdf; Lifecycle: Comp-Approve; MATERIAL: CHIP; Manuf_PN: RR0510S-472-JN; Manuf_name: CYNTEC CO.. LTD.; Manuftr: CYN; Part_Type: *LF_Resistor; Status: Preferred; TOLERANCE: 5%; WATTAGE: 1/16W; fp_ECN: 0402 SERIES_LL34.xls

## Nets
GND: C1.2 PC24.2 PC25.2 PC26.2 PC28.2 PC30.2 PC33.2 PC42.2 PC103.2 PC183.2 PC184.2 PC185.2 PC186.2 PC187.2 PC188.2 PC189.2 PC190.2 PC191.2 PC258.2 PC261.2 PC263.2 PR15.1 PR117.1 PR1411.2 PU4.1(GND) PU5.4(GND) PU7.TH(EP) Q9.1(S1) ; also on sheet 1 2 3 4 11 12 13 14 15 16 17 18 19 20 22 23 24 25 26 27 41 42 45 46 47 48 49 50 51 52 53 54 55 56 57 58 59 60 61 62 63 64 65 66 67 68 69 70 71 72 73 74 75 77 79 81 82 83 84 86 87 88 92
P1V5_PCH: PC30.1 PC103.1 PR16.2 PU7.1(VOUT1) PU7.2(VOUT2) PU7.3(VOUT3) ; also on sheet 46 47 49 52 94
P1V5_PCH_ADJ: PR15.2 PR16.1 PU7.4(ADJ)
P3V3: PC188.1 PC190.1 PR119.1 PU5.7(BLEED) PU5.9(VOUT1) PU5.10(VOUT2) PU5.11(VOUT3) PU5.12(VOUT4) ; also on sheet 4 19 20 41 42 46 47 49 50 52 55 56 63 67 74 77 81
P3V3_SR: C1.1 PU5.5(SR)
P3V3_STBY: PC184.1 PC185.1 PC186.1 PC187.1 PC189.1 PC191.1 PL16.2 PR13.1 PR14.1 PR118.1 PU5.1(VIN1) PU5.3(VCC) PU5.TH(VIN2) R1438.2 ; also on sheet 3 4 13 14 16 18 19 20 22 24 25 26 27 41 52 55 56 57 58 59 62 63 64 65 67 68 69 70 71 72 73 74 75 77 79 81 82 84 86 87 88 92
P3V3_STBY_EN: PC258.1 PJ108.2 PU4.7(EN)
P3V3_STBY_EN_S: PJ108.1 PR1411.1 PR1412.2
P3V3_STBY_FB: PR117.2 PR118.2 PU4.6(VFB)
P3V3_STBY_SS: PC183.1 PU4.5(SS)
P5V_STBY: PC33.1 PU7.10(VDD) ; also on sheet 1 2 13 23 26 70 74 84
P12V_STBY: PC25.1 PL17.1 PR1412.1 ; also on sheet 2 3 23 24 25 27 74 86
PVCCSCFUSESUS: PC42.1 PU7.7(VIN1) PU7.8(VIN2) PU7.9(VIN3) ; also on sheet 26 27 51
FM_CPLD_P1V5_PCH_EN: PC261.1 PU7.6(EN) ; also on sheet 14
FM_CPLD_P3V3_EN: PC263.1 PU5.2(EN) R1439.1
FM_CPLD_P3V3_EN_N: Q9.2(G1) ; also on sheet 14
FM_CPLD_P3V3_EN_R: Q9.6(D1) R1438.1 R1439.2
FM_CPLD_P3V3_PWRGD: R1169.2 ; also on sheet 64
FM_CPLD_P3V3_PWRGD_R: PR119.2 PU5.6(PG) R1169.1
PWRGD_P1V5_PCH: R1165.1 ; also on sheet 64
PWRGD_P1V5_PCH_R: PR14.2 PU7.5(PGOOD) R1165.2
PWRGD_P3V3_STBY_PLD: PR13.2 PU4.4(PG)
SW_P3V3_STBY_BT: PC29.1 PU4.8(VBST)
SW_P3V3_STBY_FLT: PC24.1 PC26.1 PC28.1 PL17.2 PU4.3(VIN)
SW_P3V3_STBY_PH: PC29.2 PL16.1 PU4.2(SW)

Not connected (* = marked no-connect by the designer): PU5 8(NC1)*; Q9 3(D2)* 4(S2)* 5(G2)*

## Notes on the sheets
sheet 28
- Design specification
  P3V3_STBY
  Output Voltage = 3.3V∮2%
  Output Ripple & Noise ∮11mV
  Transient Tolerance = ∮5%
  TDC = 2A
  Max current = 2.5A
  Over-Current Protection(IC Rating) = 4.2A
  Current Step = 0.5A
  Slew Rate = 1.0A/us
  Work Frequency = 650kHZ
  Efficiency > 85% @TDC
  Follow grangeville_pdg_2_2 p355
- Open Drain
  6.5V max
- VEN High > 1.6v
  VEN Low < 0.6v
- ISAT=8A
  DCR=54m
  7*6*3
- Ra
- Rb
- Vo=0.765(1+Ra/Rb)=3.304V
- P3V3_STBY
sheet 29
- BLANK
sheet 30
- SPI_STRUCTURE
sheet 31
- Design specification
  P1V5_PCH
  Output Voltage = 1.5V∮3%
  Output Ripple & Noise ∮1%
  Transient Tolerance = ∮5.0%
  TDC = 0.2A
  Max current = 0.3A
  Current Step = 0.03A
  Slew Rate = 1A/us
  PD=(1.7V-1.5V)*0.2A=0.04W
  Follow grangeville_pdg_2_2 p358
- VEN High > 1.2v
  VEN Low < 0.4v
- Ra
- Rb
- Vnom=0.8(1+Ra/Rb)= 1.5V
- NOTE:RT9059_15GQW FIX OUTPUT VOLTAGE AT 1.5V
- P1V5_PCH
sheet 32
- Design Note : Current loading for P3V3 is 2.5A.
- P3V3 SWITCH
sheet 33
- Minilake M/B
- PCB REV: C
  PCBA REV: C3A
  FAB: 3
  SCH Rev: 1.0
  LAST UPDATE: 2018/09/20
- COVER PAGE
sheet 34
- INDEX
- 001 COVER PAGE
  002 PAGE INDEX
  003 BLANK
  004 Mini Lake BLOCK DIAGRAM
  005 SMBus BLOCK DIAGRAM
  006 POWER SEQUENCE DIAGRAM_1
  007 POWER SEQUENCE DIAGRAM_2
  008 CLOCK DIAGRAM
  009 PWRGD/RSTDIAGRAM
  010 INTERRUPT/ERROR ESCALATION
  011 POWER TOPOLOGY
  012 RESET BLOCK DIAGRAM
  013 UART TOPOLOGY
  014 SPI_STRUCTURE
  015 BLANK
  016 BDE STAPPING_1
  017 BDE STAPPING_2
  018 BDX-DE DDR4 CHANNELA
  019 BDX-DE DDR4 CHANNELB
  020 BDX-DE PCIE CPU/PCH
  021 BDX-DE 10GBE LAN_1
  022 BDX-DE 10GBE LAN_2
  023 BDX-DE SATA,USB2,USB3
  024 BDX-DE LPC,SPI,GPIO,INT_1
  025 BDX-DE LPC,SPI,GPIO,INT_2
  026 BDX-DE UART,MGNT,INT,SVID_1
  027 BDX-DE UART,MGNT, NT, SVID_2
  028 BDX-DE CLK
  029 BDX-DE TEST
  030 BDX-DE MISC,SMBus
  031 BDX-DE POWER_1
  032 BDX-DE POWER_2
  033 BDX-DE GND_1
  034 BDX-DE GND_2
  035 BLANK
  036 CPU XDP_1
  037 CPU XDP_2
- 038 BLANK
  039 CPU JUMPERS
  040 ERROR CNTL_1
  041 ERROR CNTL_2
  042 CPU SPI
  043 PLTRST_BUFFER
  044 SPI MUX
  045 DDR4 SODIMM CHA_1
  046 DDR4 SODIMM CHA_2
  047 DDR4 SODIMM CHB_1
  048 DDR4 SODIMM CHB_1
  049 TPM  SLB9670
  050 BLANK
  051 CPLD_1
  052 CPLD_2
  053 COM-E_TYPE7_AB_1
  054 COM-E_TYPE7_AB_2
  055 COM-E_TYPE7_CD_1
  056 COM-E_TYPE7_CD_2
  057 LEVEL SHIFT
  058 SYS_SENSOR
  059 PWR_SYSRSY_BUTTON
  060 BEBUG UART
  061 SNOWFLAKE_1
  062 SNOWFLAKE_2
  063 SNOWFLAKE_3
  064 VOLTAGE MONITOR
  065 SMBUS ISOLATOR
  066 PWR_PORT80 LED
  067 DELTA-L AND TDR_1
  068 DELTA-L AND TDR_2
  069 DELTA-L AND TDR_3
  070 RSMRST_SYSRST
  071 ISOLATOR_1
  072 ISOLATOR_2
  073 MDC/MDIO
  074 POWER SENSING INA230
- 075 I210 GbE PHY PCIE,MDI
  076 I210 GbE PHY JTAG,SPI,POWER
  077 SCREW
  078 BLANK
  079 P3V3_STBY
  080 PVCCSCFUSESUS
  081 P2V5_VPP
  082 PCCKRHV
  083 P1V5_PCH
  084 PVCCIN & P1V05_COMBINED_1
  085 PVCCIN & P1V05_COMBINED_2
  086 PVCCIN & P1V05_COMBINED_3
  087 PV_VDDRAB_1
  088 PV_VDDRAB_2
  089 PV_DDR_VTTAB
  090 P3V3 SWITCH
  091 P1V05_PCH  SWITCH
  092 BLANK
  093 TP RESERVE FOR ICT
  094 BLANK
  095 BLANK
- PAGE INDEX
sheet 35
- BLANK
sheet 36
- SMBUS BLOCK DIAGRAM
sheet 37
- POWER SQUENCE DIAGRAM_1
sheet 38
- CLOCK DIAGRAM
sheet 39
- UART DIAGRAM
